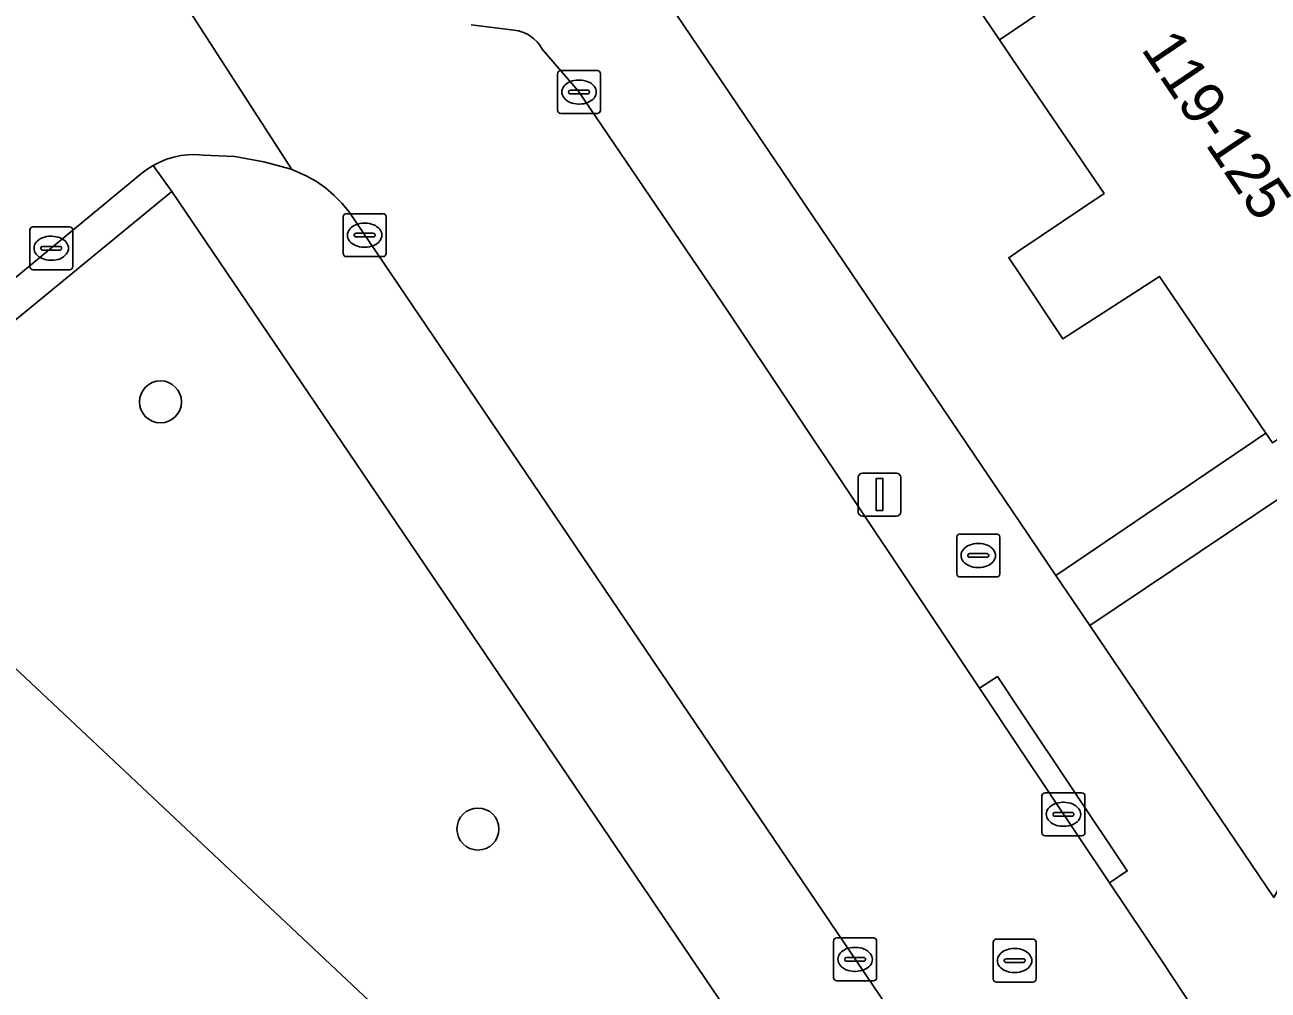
# Model space of a CAD drawing. Extents: x 159888 to 160761, y 384031 to 384750.
# Drawn here: x 160476.83 to 160505.78, y 384185.68 to 384208.16 of the extents above; entities that cross this region are included whole.
import ezdxf

# ---------------------------------------------------------------- set-up
doc = ezdxf.new("R2010")
doc.units = 0
for name, color, linetype in [('IMGEO_Boom', 7, 'Continuous'), ('IMGEO_Brandkraan', 7, 'Continuous'), ('IMGEO_Erf', 7, 'Continuous'), ('IMGEO_Groenvoorziening', 7, 'Continuous'), ('IMGEO_Kolk', 7, 'Continuous'), ('IMGEO_Lichtmast', 7, 'Continuous'), ('IMGEO_Pand', 7, 'Continuous'), ('IMGEO_Pand_nummerreeks', 7, 'Continuous'), ('IMGEO_Rijbaan_lokaal_open', 7, 'Continuous'), ('IMGEO_Rioolput', 7, 'Continuous'), ('IMGEO_Voetpad_open', 7, 'Continuous')]:
    doc.layers.add(name, color=color, linetype=linetype)

msp = doc.modelspace()

# ---------------------------------------------------------------- linework, layer by layer
at = {"layer": 'IMGEO_Boom'}
for centre in [(160479.991, 384199.377), (160487.383, 384189.429)]:
    msp.add_circle(centre, 0.489, dxfattribs=at)
at = {"layer": 'IMGEO_Brandkraan'}
for p, q in [((160498.532, 384195.374), (160498.532, 384196.226)), ((160498.607, 384196.3), (160499.459, 384196.3)), ((160499.02, 384196.08), (160499.045, 384196.08)), ((160499.533, 384196.226), (160499.533, 384195.374)), ((160498.791, 384195.794), (160498.791, 384195.806)), ((160499.229, 384195.757), (160498.831, 384195.757)), ((160498.834, 384195.843), (160499.232, 384195.843)), ((160499.275, 384195.806), (160499.275, 384195.794)), ((160499.043, 384195.52), (160499.018, 384195.52)), ((160499.459, 384195.3), (160498.607, 384195.3))]:
    msp.add_line(p, q, dxfattribs=at)
for points in [[(160498.532, 384195.374), (160498.532, 384196.226)], [(160498.607, 384196.3), (160499.459, 384196.3)], [(160499.533, 384196.226), (160499.533, 384195.374)], [(160499.459, 384195.3), (160498.607, 384195.3)]]:
    msp.add_lwpolyline(points, dxfattribs=at)
for centre, radius, start, end in [((160498.609, 384196.224), 0.0765, 91.552, 178.448), ((160498.609, 384196.224), 0.0765, 91.552, 178.448), ((160499.457, 384196.224), 0.0765, 1.552, 88.448), ((160499.457, 384196.224), 0.0765, 1.552, 88.448), ((160498.831, 384195.803), 0.0403, 85.8775, 175.7526), ((160498.828, 384195.793), 0.0366, 178.938, 274.7102), ((160499.232, 384195.8), 0.043, 264.8664, 352.4533), ((160499.236, 384195.805), 0.0386, 1.7309, 96.639), ((160498.609, 384195.376), 0.0765, 181.552, 268.448), ((160498.609, 384195.376), 0.0765, 181.552, 268.448), ((160499.457, 384195.376), 0.0765, 271.552, 358.448), ((160499.457, 384195.376), 0.0765, 271.552, 358.448)]:
    msp.add_arc(centre, radius, start, end, dxfattribs=at)
for centre, major_axis, ratio, start_param, end_param in [((160499.019, 384195.8), (-0.387, 0.002), 0.722429, 4.712389, 7.853982), ((160499.044, 384195.8), (-0.39, 0.002), 0.717154, 1.570796, 4.712389)]:
    msp.add_ellipse(centre, major_axis=major_axis, ratio=ratio, start_param=start_param, end_param=end_param, dxfattribs=at)
at = {"layer": 'IMGEO_Erf'}
msp.add_lwpolyline([(160463.867, 384250), (160500, 384196.578), (160500.839, 384195.337), (160505.731, 384198.646), (160503.249, 384202.298), (160501.003, 384200.844), (160500, 384202.348), (160499.742, 384202.732), (160500, 384202.907), (160501.96, 384204.231), (160499.995, 384207.116), (160499.527, 384207.807), (160497.118, 384211.369)], dxfattribs=at)
at = {"layer": 'IMGEO_Groenvoorziening'}
msp.add_lwpolyline([(160480.257, 384204.274), (160469.497, 384195.444), (160472.691, 384191.58), (160475.677, 384194.048), (160486.78, 384183.613), (160491.144, 384179.427), (160491.067, 384179.347), (160492.813, 384177.71), (160494.41, 384176.424), (160494.765, 384176.208), (160495.213, 384176.159), (160496.371, 384176.297), (160496.006, 384179.357), (160495.925, 384180.003), (160495.787, 384180.64), (160495.592, 384181.262), (160495.343, 384181.864), (160495.041, 384182.441), (160494.689, 384182.989), (160494.565, 384183.158)], close=True, dxfattribs=at)
msp.add_lwpolyline([(160496.371, 384176.297), (160495.213, 384176.159), (160494.765, 384176.208), (160494.41, 384176.424), (160492.813, 384177.71), (160491.169, 384175.986), (160489.431, 384177.643), (160489.36, 384177.569), (160485.029, 384181.774), (160486.78, 384183.613), (160475.677, 384194.048), (160472.691, 384191.58), (160442.427, 384166.564)], dxfattribs=at)
at = {"layer": 'IMGEO_Kolk'}
for p, q in [((160489.311, 384207.092), (160490.163, 384207.092)), ((160489.236, 384206.166), (160489.236, 384207.018)), ((160489.724, 384206.872), (160489.749, 384206.872)), ((160490.237, 384207.018), (160490.237, 384206.166)), ((160489.495, 384206.586), (160489.495, 384206.598)), ((160489.933, 384206.549), (160489.535, 384206.549)), ((160489.538, 384206.635), (160489.936, 384206.635)), ((160489.979, 384206.598), (160489.979, 384206.586)), ((160489.747, 384206.312), (160489.722, 384206.312)), ((160490.163, 384206.092), (160489.311, 384206.092)), ((160484.244, 384202.834), (160484.244, 384203.686)), ((160484.319, 384203.76), (160485.171, 384203.76)), ((160485.245, 384203.686), (160485.245, 384202.834)), ((160476.947, 384202.529), (160476.947, 384203.381)), ((160477.022, 384203.455), (160477.874, 384203.455)), ((160477.948, 384203.381), (160477.948, 384202.529)), ((160484.503, 384203.254), (160484.503, 384203.266)), ((160484.546, 384203.303), (160484.944, 384203.303)), ((160484.732, 384203.54), (160484.757, 384203.54)), ((160484.987, 384203.266), (160484.987, 384203.254)), ((160477.249, 384202.998), (160477.647, 384202.998)), ((160477.435, 384203.235), (160477.46, 384203.235)), ((160484.941, 384203.217), (160484.543, 384203.217)), ((160484.755, 384202.98), (160484.73, 384202.98)), ((160477.206, 384202.949), (160477.206, 384202.961)), ((160477.644, 384202.912), (160477.246, 384202.912)), ((160477.69, 384202.961), (160477.69, 384202.949)), ((160485.171, 384202.76), (160484.319, 384202.76)), ((160477.874, 384202.455), (160477.022, 384202.455)), ((160477.458, 384202.675), (160477.433, 384202.675)), ((160500.59, 384190.273), (160501.442, 384190.273)), ((160500.515, 384189.347), (160500.515, 384190.199)), ((160501.003, 384190.053), (160501.028, 384190.053)), ((160501.516, 384190.199), (160501.516, 384189.347)), ((160500.774, 384189.767), (160500.774, 384189.779)), ((160501.212, 384189.73), (160500.814, 384189.73)), ((160500.817, 384189.816), (160501.215, 384189.816)), ((160501.258, 384189.779), (160501.258, 384189.767)), ((160501.026, 384189.493), (160501.001, 384189.493)), ((160501.442, 384189.273), (160500.59, 384189.273)), ((160495.664, 384185.968), (160495.664, 384186.82)), ((160495.739, 384186.894), (160496.591, 384186.894)), ((160496.665, 384186.82), (160496.665, 384185.968)), ((160496.152, 384186.674), (160496.177, 384186.674)), ((160495.923, 384186.388), (160495.923, 384186.4)), ((160496.361, 384186.351), (160495.963, 384186.351)), ((160495.966, 384186.437), (160496.364, 384186.437)), ((160496.407, 384186.4), (160496.407, 384186.388)), ((160496.591, 384185.894), (160495.739, 384185.894)), ((160496.175, 384186.114), (160496.15, 384186.114))]:
    msp.add_line(p, q, dxfattribs=at)
for points in [[(160489.311, 384207.092), (160490.163, 384207.092)], [(160489.236, 384206.166), (160489.236, 384207.018)], [(160490.237, 384207.018), (160490.237, 384206.166)], [(160490.163, 384206.092), (160489.311, 384206.092)], [(160484.244, 384202.834), (160484.244, 384203.686)], [(160484.319, 384203.76), (160485.171, 384203.76)], [(160485.245, 384203.686), (160485.245, 384202.834)], [(160476.947, 384202.529), (160476.947, 384203.381)], [(160477.022, 384203.455), (160477.874, 384203.455)], [(160477.948, 384203.381), (160477.948, 384202.529)], [(160485.171, 384202.76), (160484.319, 384202.76)], [(160477.874, 384202.455), (160477.022, 384202.455)], [(160500.59, 384190.273), (160501.442, 384190.273)], [(160500.515, 384189.347), (160500.515, 384190.199)], [(160501.516, 384190.199), (160501.516, 384189.347)], [(160501.442, 384189.273), (160500.59, 384189.273)], [(160495.664, 384185.968), (160495.664, 384186.82)], [(160495.739, 384186.894), (160496.591, 384186.894)], [(160496.665, 384186.82), (160496.665, 384185.968)], [(160496.591, 384185.894), (160495.739, 384185.894)]]:
    msp.add_lwpolyline(points, dxfattribs=at)
for centre, radius, start, end in [((160489.313, 384207.016), 0.0765, 91.552, 178.448), ((160489.313, 384207.016), 0.0765, 91.552, 178.448), ((160490.161, 384207.016), 0.0765, 1.552, 88.448), ((160490.161, 384207.016), 0.0765, 1.552, 88.448), ((160489.535, 384206.595), 0.0403, 85.8775, 175.7526), ((160489.532, 384206.585), 0.0366, 178.938, 274.7102), ((160489.936, 384206.592), 0.043, 264.8664, 352.4533), ((160489.94, 384206.597), 0.0386, 1.7309, 96.639), ((160489.313, 384206.168), 0.0765, 181.552, 268.448), ((160489.313, 384206.168), 0.0765, 181.552, 268.448), ((160490.161, 384206.168), 0.0765, 271.552, 358.448), ((160490.161, 384206.168), 0.0765, 271.552, 358.448), ((160484.321, 384203.684), 0.0765, 91.552, 178.448), ((160484.321, 384203.684), 0.0765, 91.552, 178.448), ((160485.169, 384203.684), 0.0765, 1.552, 88.448), ((160485.169, 384203.684), 0.0765, 1.552, 88.448), ((160477.024, 384203.379), 0.0765, 91.552, 178.448), ((160477.024, 384203.379), 0.0765, 91.552, 178.448), ((160477.872, 384203.379), 0.0765, 1.552, 88.448), ((160477.872, 384203.379), 0.0765, 1.552, 88.448), ((160484.543, 384203.263), 0.0403, 85.8775, 175.7526), ((160484.948, 384203.265), 0.0386, 1.7309, 96.639), ((160477.246, 384202.958), 0.0403, 85.8775, 175.7526), ((160477.651, 384202.96), 0.0386, 1.7309, 96.639), ((160484.54, 384203.253), 0.0366, 178.938, 274.7102), ((160484.944, 384203.26), 0.043, 264.8664, 352.4533), ((160477.243, 384202.948), 0.0366, 178.938, 274.7102), ((160477.647, 384202.955), 0.043, 264.8664, 352.4533), ((160484.321, 384202.836), 0.0765, 181.552, 268.448), ((160484.321, 384202.836), 0.0765, 181.552, 268.448), ((160485.169, 384202.836), 0.0765, 271.552, 358.448), ((160485.169, 384202.836), 0.0765, 271.552, 358.448), ((160477.024, 384202.531), 0.0765, 181.552, 268.448), ((160477.024, 384202.531), 0.0765, 181.552, 268.448), ((160477.872, 384202.531), 0.0765, 271.552, 358.448), ((160477.872, 384202.531), 0.0765, 271.552, 358.448), ((160500.592, 384190.197), 0.0765, 91.552, 178.448), ((160500.592, 384190.197), 0.0765, 91.552, 178.448), ((160501.44, 384190.197), 0.0765, 1.552, 88.448), ((160501.44, 384190.197), 0.0765, 1.552, 88.448), ((160500.814, 384189.776), 0.0403, 85.8775, 175.7526), ((160500.811, 384189.766), 0.0366, 178.938, 274.7102), ((160501.215, 384189.773), 0.043, 264.8664, 352.4533), ((160501.219, 384189.778), 0.0386, 1.7309, 96.639), ((160500.592, 384189.349), 0.0765, 181.552, 268.448), ((160500.592, 384189.349), 0.0765, 181.552, 268.448), ((160501.44, 384189.349), 0.0765, 271.552, 358.448), ((160501.44, 384189.349), 0.0765, 271.552, 358.448), ((160495.741, 384186.818), 0.0765, 91.552, 178.448), ((160495.741, 384186.818), 0.0765, 91.552, 178.448), ((160496.589, 384186.818), 0.0765, 1.552, 88.448), ((160496.589, 384186.818), 0.0765, 1.552, 88.448), ((160495.963, 384186.397), 0.0403, 85.8775, 175.7526), ((160495.96, 384186.387), 0.0366, 178.938, 274.7102), ((160496.364, 384186.394), 0.043, 264.8664, 352.4533), ((160496.368, 384186.399), 0.0386, 1.7309, 96.639), ((160495.741, 384185.97), 0.0765, 181.552, 268.448), ((160495.741, 384185.97), 0.0765, 181.552, 268.448), ((160496.589, 384185.97), 0.0765, 271.552, 358.448), ((160496.589, 384185.97), 0.0765, 271.552, 358.448)]:
    msp.add_arc(centre, radius, start, end, dxfattribs=at)
for centre, major_axis, ratio, start_param, end_param in [((160489.723, 384206.592), (-0.387, 0.002), 0.722429, 4.712389, 7.853982), ((160489.748, 384206.592), (-0.39, 0.002), 0.717154, 1.570796, 4.712389), ((160484.731, 384203.26), (-0.387, 0.002), 0.722429, 4.712389, 7.853982), ((160484.756, 384203.26), (-0.39, 0.002), 0.717154, 1.570796, 4.712389), ((160477.434, 384202.955), (-0.387, 0.002), 0.722429, 4.712389, 7.853982), ((160477.459, 384202.955), (-0.39, 0.002), 0.717154, 1.570796, 4.712389), ((160501.002, 384189.773), (-0.387, 0.002), 0.722429, 4.712389, 7.853982), ((160501.027, 384189.773), (-0.39, 0.002), 0.717154, 1.570796, 4.712389), ((160496.151, 384186.394), (-0.387, 0.002), 0.722429, 4.712389, 7.853982), ((160496.176, 384186.394), (-0.39, 0.002), 0.717154, 1.570796, 4.712389)]:
    msp.add_ellipse(centre, major_axis=major_axis, ratio=ratio, start_param=start_param, end_param=end_param, dxfattribs=at)
at = {"layer": 'IMGEO_Lichtmast'}
for p, q in [((160496.237, 384196.819), (160496.237, 384197.619)), ((160496.237, 384197.619), (160496.237, 384196.819)), ((160496.337, 384197.719), (160497.127, 384197.719)), ((160497.127, 384197.719), (160496.337, 384197.719)), ((160497.227, 384197.619), (160497.227, 384196.819)), ((160497.227, 384196.819), (160497.227, 384197.619)), ((160497.127, 384196.719), (160496.337, 384196.719)), ((160496.337, 384196.719), (160497.127, 384196.719))]:
    msp.add_line(p, q, dxfattribs=at)
msp.add_lwpolyline([(160496.657, 384197.594), (160496.807, 384197.594), (160496.807, 384196.844), (160496.657, 384196.844), (160496.657, 384197.594)], dxfattribs=at)
for centre, start, end in [((160496.337, 384197.619), 90, 180), ((160496.337, 384197.619), 90, 180), ((160497.127, 384197.619), 0, 90), ((160497.127, 384197.619), 360, 90), ((160496.337, 384196.819), 180, 270), ((160496.337, 384196.819), 180, 270), ((160497.127, 384196.819), 270, 0), ((160497.127, 384196.819), 270, 0)]:
    msp.add_arc(centre, 0.1, start, end, dxfattribs=at)
at = {"layer": 'IMGEO_Pand'}
for points in [[(160500.631, 384221.901), (160493.342, 384216.973), (160495.735, 384213.434), (160493.487, 384211.914), (160494.88, 384209.855), (160497.118, 384211.369), (160499.527, 384207.807), (160506.796, 384212.725), (160505.091, 384215.245), (160503.637, 384217.422), (160504.179, 384217.784), (160502.946, 384219.608), (160502.417, 384219.25)], [(160510.84, 384205.909), (160511.753, 384206.604), (160509.1, 384210.528), (160508.539, 384210.148), (160506.796, 384212.725), (160499.527, 384207.807), (160499.995, 384207.116), (160501.96, 384204.231), (160500, 384202.907), (160499.742, 384202.732), (160500, 384202.348), (160501.003, 384200.844), (160503.249, 384202.298), (160505.731, 384198.646), (160505.883, 384198.422), (160506.276, 384198.688), (160506.138, 384198.891), (160510.28, 384201.693), (160512.14, 384202.951), (160512.409, 384202.82), (160512.758, 384203.056), (160512.59, 384203.306)]]:
    msp.add_lwpolyline(points, close=True, dxfattribs=at)
at = {"layer": 'IMGEO_Rijbaan_lokaal_open'}
for points in [[(160446.201, 384260.194), (160453.631, 384249.222), (160476.697, 384215.312), (160476.89, 384215.003), (160477.055, 384214.679), (160477.189, 384214.34), (160477.293, 384213.991), (160477.366, 384213.634), (160477.37, 384213.596), (160483.05, 384204.786), (160483.161, 384204.745), (160483.396, 384204.636), (160483.62, 384204.507), (160483.831, 384204.358), (160484.029, 384204.191), (160484.21, 384204.007), (160484.375, 384203.808), (160497.404, 384184.565)], [(160479.56, 384204.703), (160479.676, 384204.79), (160479.821, 384204.883), (160479.975, 384204.961), (160480.134, 384205.026), (160480.299, 384205.076), (160480.468, 384205.112), (160480.639, 384205.132), (160480.811, 384205.137), (160480.983, 384205.126), (160481.722, 384205.092), (160482.401, 384204.969), (160483, 384204.805), (160483.05, 384204.786), (160477.37, 384213.596), (160477.406, 384213.272), (160477.414, 384212.908), (160477.389, 384212.545), (160477.332, 384212.185), (160477.243, 384211.832), (160477.122, 384211.488), (160476.972, 384211.156), (160476.792, 384210.839)], [(160488.221, 384208.033), (160487.222, 384208.157)], [(160505.94, 384180.299), (160505.629, 384181.607), (160505.201, 384182.882), (160504.662, 384184.113), (160504.014, 384185.292), (160503.336, 384186.31), (160502.084, 384188.18), (160500, 384191.296), (160499.06, 384192.709), (160497.556, 384194.968), (160493.2, 384201.491), (160489.717, 384206.618), (160488.881, 384207.593)], [(160444.925, 384176.05), (160446.709, 384177.549), (160479.56, 384204.703)]]:
    msp.add_lwpolyline(points, dxfattribs=at)
msp.add_lwpolyline([(160521.408, 384199.653), (160528.376, 384199.541), (160528.398, 384200.916), (160528.444, 384203.805), (160529.565, 384203.787), (160529.523, 384206.005), (160528.042, 384208.159), (160526.284, 384210.714), (160526.072, 384210.572), (160501.631, 384194.166), (160505.914, 384187.834), (160506.667, 384189.198), (160506.713, 384192.087), (160514.101, 384191.968), (160514.113, 384192.72), (160514.159, 384195.609), (160521.342, 384195.493), (160521.362, 384196.764)], close=True, dxfattribs=at)
msp.add_arc((160488.13, 384207.181), 0.857, 28.7282, 83.8917, dxfattribs=at)
at = {"layer": 'IMGEO_Rioolput'}
for p, q in [((160499.378, 384185.941), (160499.378, 384186.793)), ((160499.453, 384186.867), (160500.305, 384186.867)), ((160500.379, 384186.793), (160500.379, 384185.941)), ((160499.866, 384186.647), (160499.891, 384186.647)), ((160499.637, 384186.361), (160499.637, 384186.373)), ((160500.075, 384186.324), (160499.677, 384186.324)), ((160499.68, 384186.41), (160500.078, 384186.41)), ((160500.121, 384186.373), (160500.121, 384186.361)), ((160499.889, 384186.087), (160499.864, 384186.087)), ((160500.305, 384185.867), (160499.453, 384185.867))]:
    msp.add_line(p, q, dxfattribs=at)
for points in [[(160499.378, 384185.941), (160499.378, 384186.793)], [(160499.453, 384186.867), (160500.305, 384186.867)], [(160500.379, 384186.793), (160500.379, 384185.941)], [(160500.305, 384185.867), (160499.453, 384185.867)]]:
    msp.add_lwpolyline(points, dxfattribs=at)
for centre, radius, start, end in [((160499.455, 384186.791), 0.0765, 91.552, 178.448), ((160499.455, 384186.791), 0.0765, 91.552, 178.448), ((160500.303, 384186.791), 0.0765, 1.552, 88.448), ((160500.303, 384186.791), 0.0765, 1.552, 88.448), ((160499.677, 384186.37), 0.0403, 85.8775, 175.7526), ((160499.674, 384186.36), 0.0366, 178.938, 274.7102), ((160500.078, 384186.367), 0.043, 264.8664, 352.4533), ((160500.082, 384186.372), 0.0386, 1.7309, 96.639), ((160499.455, 384185.943), 0.0765, 181.552, 268.448), ((160499.455, 384185.943), 0.0765, 181.552, 268.448), ((160500.303, 384185.943), 0.0765, 271.552, 358.448), ((160500.303, 384185.943), 0.0765, 271.552, 358.448)]:
    msp.add_arc(centre, radius, start, end, dxfattribs=at)
for centre, major_axis, ratio, start_param, end_param in [((160499.865, 384186.367), (-0.387, 0.002), 0.722429, 4.712389, 7.853982), ((160499.89, 384186.367), (-0.39, 0.002), 0.717154, 1.570796, 4.712389)]:
    msp.add_ellipse(centre, major_axis=major_axis, ratio=ratio, start_param=start_param, end_param=end_param, dxfattribs=at)
at = {"layer": 'IMGEO_Voetpad_open'}
for points in [[(160505.914, 384187.834), (160501.631, 384194.166), (160500.839, 384195.337), (160500, 384196.578), (160463.867, 384250)], [(160505.883, 384198.422), (160505.731, 384198.646), (160500.839, 384195.337), (160501.631, 384194.166), (160526.072, 384210.572)], [(160487.222, 384208.157), (160488.221, 384208.033)], [(160488.881, 384207.593), (160489.717, 384206.618), (160493.2, 384201.491), (160497.556, 384194.968), (160499.06, 384192.709), (160499.476, 384192.985), (160500, 384192.201), (160502.5, 384188.456), (160502.084, 384188.18), (160503.336, 384186.31), (160504.014, 384185.292), (160504.662, 384184.113), (160505.201, 384182.882), (160505.629, 384181.607), (160505.94, 384180.299)], [(160497.404, 384184.565), (160484.375, 384203.808), (160484.21, 384204.007), (160484.029, 384204.191), (160483.831, 384204.358), (160483.62, 384204.507), (160483.396, 384204.636), (160483.161, 384204.745), (160483.05, 384204.786), (160483, 384204.805), (160482.401, 384204.969), (160481.722, 384205.092), (160480.983, 384205.126), (160480.811, 384205.137), (160480.639, 384205.132), (160480.468, 384205.112), (160480.299, 384205.076), (160480.134, 384205.026), (160479.975, 384204.961), (160479.821, 384204.883), (160480.257, 384204.274), (160494.565, 384183.158)], [(160480.257, 384204.274), (160479.821, 384204.883), (160479.676, 384204.79), (160479.56, 384204.703), (160446.709, 384177.549), (160444.925, 384176.05)], [(160443.257, 384174.333), (160443.5, 384174.087), (160445.254, 384175.551), (160469.497, 384195.444), (160480.257, 384204.274)]]:
    msp.add_lwpolyline(points, dxfattribs=at)
msp.add_lwpolyline([(160502.084, 384188.18), (160502.5, 384188.456), (160500, 384192.201), (160499.476, 384192.985), (160499.06, 384192.709), (160500, 384191.296)], close=True, dxfattribs=at)
msp.add_arc((160488.13, 384207.181), 0.857, 28.7282, 83.8917, dxfattribs=at)

# ---------------------------------------------------------------- texts
at = {"layer": 'IMGEO_Pand_nummerreeks'}
msp.add_text('119-125', height=1, rotation=304.0163, dxfattribs=at).set_placement((160502.807, 384207.593))

doc.saveas('drawing.dxf')
